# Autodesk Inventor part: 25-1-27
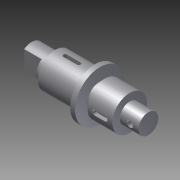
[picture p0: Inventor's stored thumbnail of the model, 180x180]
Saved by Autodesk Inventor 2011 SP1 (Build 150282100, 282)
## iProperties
Created: 2014-01
Part Number: 25-1-27
Document SubType Name: Modeling
Designer: Administrator
Density: 1 g/cm^3
Author: Administrator
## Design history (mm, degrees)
sketch "草图1"
  geometry: L1 (0, 0)-(0, 10); L2 (0, 10)-(19, 10); L3 (19, 10)-(19, 14); L4 (19, 14)-(47, 14); L5 (47, 14)-(47, 10); L6 (47, 10)-(51, 10); L7 (51, 10)-(51, 20); L8 (51, 20)-(55, 20); L9 (55, 20)-(55, 10); L10 (55, 10)-(59, 10); L11 (59, 10)-(59, 14); L12 (59, 14)-(79, 14); L13 (79, 14)-(79, 8); L14 (79, 8)-(94, 8); L15 (94, 8)-(94, 0); L16 (94, 0)-(0, 0)
  constraints: 32 end point, 7 parallel, 6 perpendicular, 2 point on line, 1 vertical
  dimensions: "d0" = 10 distance of L1.start L1.end; "d1" = 19 distance of L1.end L2.end; "d2" = 4 distance of L2.end L3.end; "d3" = 28 distance of L3.end L4.end; "d4" = 4 distance of L4.end L5.end; "d5" = 4 distance of L5.end L6.end; "d6" = 10 distance of L6.end L7.end; "d7" = 4 distance of L7.end L8.end; "d8" = 4 distance of L9.end L10.end; "d9" = 4 distance of L10.end L11.end; "d10" = 20 distance of L11.end L12.end; "d11" = 6 distance of L12.end L13.end; "d12" = 15 distance of L13.end L14.end
revolve "旋转1" sketch "草图1" stored, may be unused: angle "d13" = 90 deg
sketch "草图2"
  geometry: L1 (-8, 6)-(8, 6); L2 (8, -6)-(-8, -6); A1 r 10 centre (0, 0) between (8, 6) and (-8, 6) reference; 2 further points
  constraints: 4 end point, 4 point on circle, 1 horizontal, 1 horizontal alignment, 1 parallel, 1 vertical alignment
extrude "拉伸1" cut sketch "草图2" distance "d15" = 14; taper "d16" = 0 deg
mirror "镜像1"
node "工作平面1"
sketch "草图3"
  geometry: L1 (19, -14)-(19, 14) reference; L2 (27, 1.5)-(38, 1.5); L3 (38, -1.5)-(27, -1.5); A1 r 1.5 centre (27, 0) between (27, 1.5) and (27, -1.5); A2 r 1.5 centre (38, 0) between (38, -1.5) and (38, 1.5); 1 further point
  constraints: 4 end point, 4 point on circle, 2 centre point, 2 tangent, 1 perpendicular
  dimensions: "d18" = 3 diameter of A1; "d19" = 8 distance from line of L1 A1.centre; "d20" = 11 distance of L2.start L2.end
extrude "拉伸2" cut sketch "草图3" stored distance "d21" = 14; taper "d22" = 0 deg
node "工作平面2"
sketch "草图4"
  geometry: L1 (-79, 14)-(-79, -14) reference; L2 (-73, -2)-(-69, -2); L3 (-69, 2)-(-73, 2); L4 (-69, 2)-(-65, 2); L5 (-65, -2)-(-69, -2); A1 r 2 centre (-73, 0) between (-73, 2) and (-73, -2); A2 r 2 centre (-65, 0) between (-65, -2) and (-65, 2); 1 further point
  constraints: 8 end point, 4 point on circle, 2 centre point, 2 tangent, 1 perpendicular
  dimensions: "d24" = 4 diameter of A1; "d25" = 6 distance from line of L1 A1.centre; "d26" = 4 distance of L2.start L2.end; "d27" = 4 distance of L2.end L3.start
extrude "拉伸3" cut sketch "草图4" distance "d28" = 3; taper "d29" = 0 deg
node "工作平面3"
sketch "草图5"
  geometry: L1 (-94, 8)-(-94, -8) reference; 2 further points
  dimensions: "d31" = 7 distance from line of L1 point (-87, 0)
hole "Hole1" sketch "草图5" at (-87, 0) diameter "d32" = 5; stored, may be unused: countersink angle "d36" = 90 deg, drill point angle "d38" = 118 deg; dims "d33" = 6, "d34" = 4, "d35" = 2, "d37" = 8
node "实体1"
other parameters: "d17" = 14, "d23" = -14, "d30" = -8
